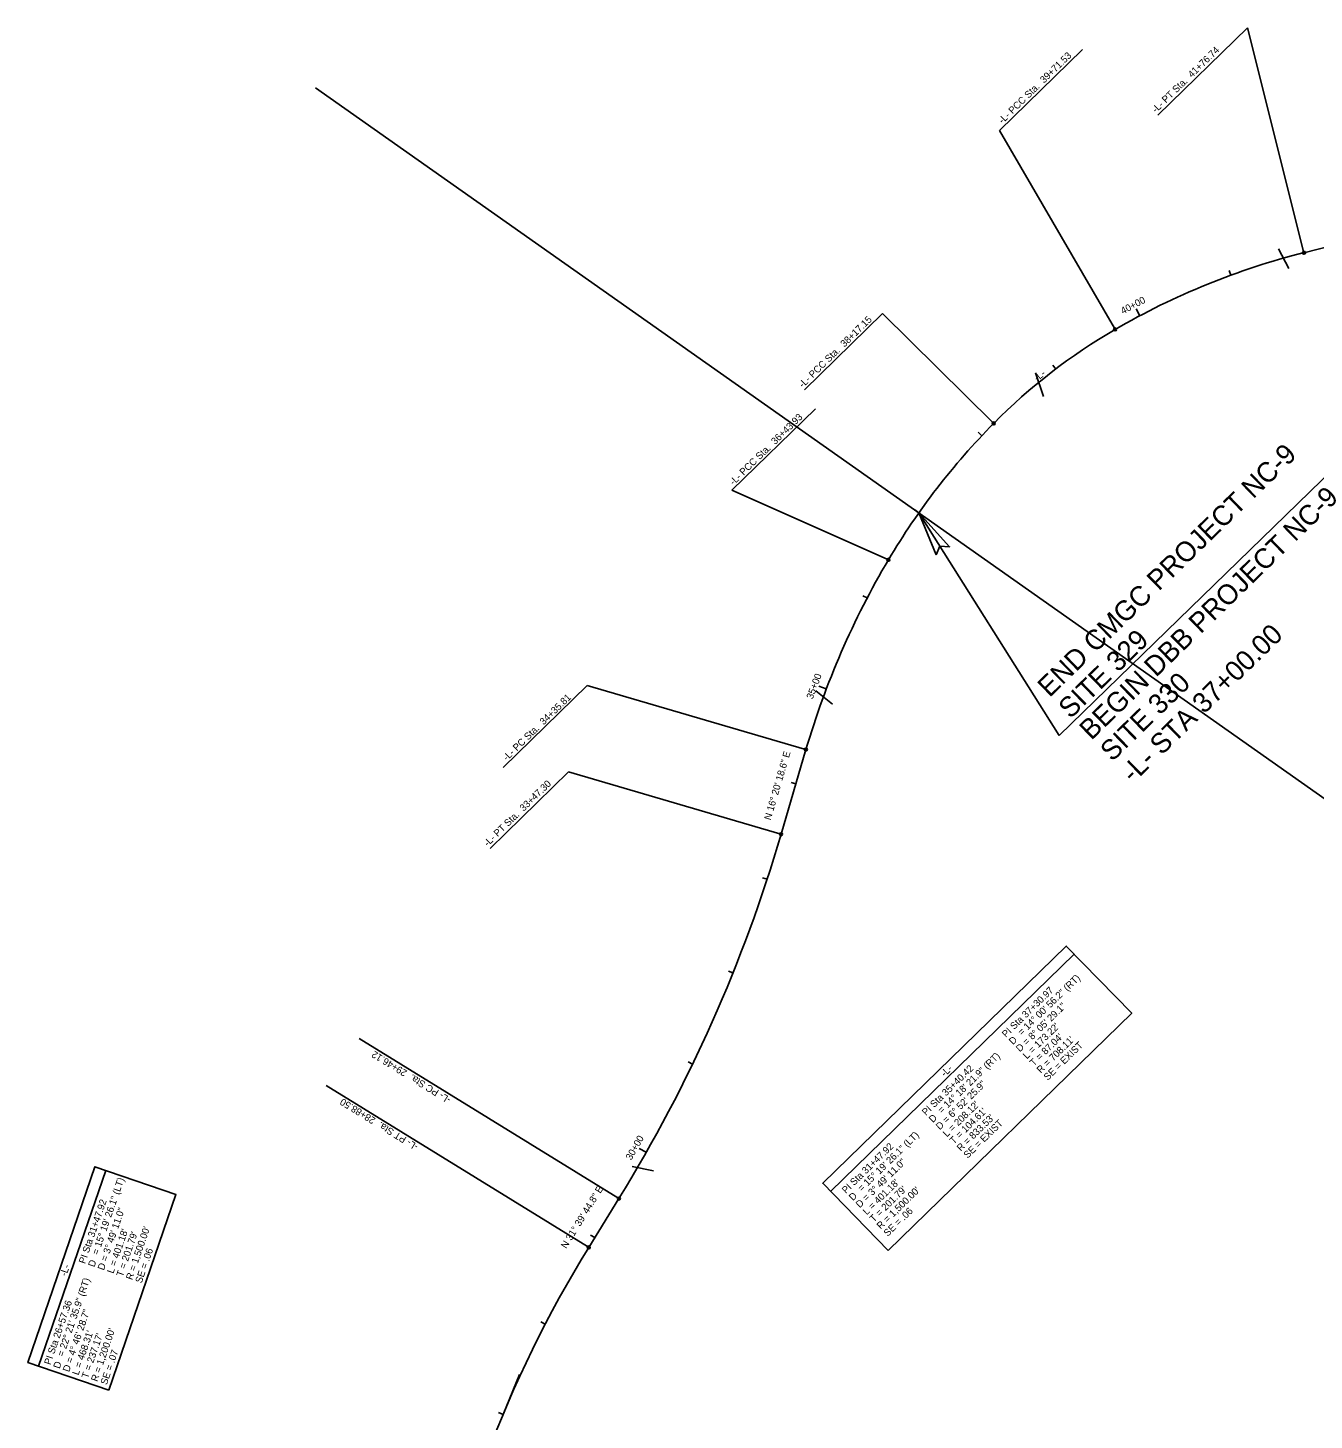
# Model space of a CAD drawing. Extents: x 1019959 to 1023888, y 635993 to 644996.
# Drawn here: x 1020284 to 1021574, y 637770 to 639166 of the extents above; entities that cross this region are included whole.
import ezdxf

# ---------------------------------------------------------------- set-up
doc = ezdxf.new("R2010")
doc.units = 0
for name, color, linetype in [('Cogo Default Point CELL', 7, 'Continuous'), ('COGO Default Point Elevation', 7, 'Continuous'), ('COGO Default Point Number', 7, 'Continuous'), ('Exist Other Culture Well CELL', 7, 'Continuous'), ('Exist Roads EOT', 7, 'Continuous'), ('Exist Structure Minor Pipes CMP 18 Inch Cogo Comment', 7, 'Continuous'), ('Exist Structure Minor Pipes CMP 18 Inch Cogo Number', 7, 'Continuous'), ('Exist Structure Minor Pipes CMP 24 Inch Cogo Number', 7, 'Continuous'), ('Exist Structure Minor Pipes CMP 24 Inch Cogo Point CELL', 7, 'Continuous'), ('Exist Utilities Power Pole CELL', 7, 'Continuous'), ('Exist Utilities Power Pole Cogo Elevation', 7, 'Continuous'), ('Exist Utilities Power Pole Cogo Number', 7, 'Continuous')]:
    doc.layers.add(name, color=color, linetype=linetype)

msp = doc.modelspace()

# ---------------------------------------------------------------- linework, layer by layer
at = {"layer": 'COGO Default Point Elevation'}
for p, q in [((1021490.3, 638918.1), (1021488.6, 638922.8)), ((1021314.7, 638824), (1021311.6, 638828)), ((1021240.5, 638757.1), (1021236.9, 638760.5)), ((1021177.3, 638679.7), (1021173.3, 638682.6)), ((1021125.5, 638594.3), (1021121.1, 638596.6)), ((1021054.1, 638407.9), (1021049.3, 638409.3)), ((1021025.2, 638312.2), (1021020.5, 638313.7)), ((1020990.9, 638218.2), (1020986.3, 638220.1)), ((1020950.5, 638126.8), (1020946, 638129)), ((1020852.3, 637952.7), (1020848.1, 637955.3)), ((1020802.7, 637865.9), (1020798.2, 637868.2)), ((1020760.3, 637775.3), (1020755.7, 637777.3))]:
    msp.add_line(p, q, dxfattribs=at)
at = {"layer": 'COGO Default Point Number'}
for p, q in [((1021399.1, 638877.5), (1021395.3, 638884.5)), ((1021084.5, 638503.1), (1021077.1, 638505.9)), ((1020904, 638038.3), (1020897, 638042.2))]:
    msp.add_line(p, q, dxfattribs=at)
at = {"layer": 'Exist Other Culture Well CELL'}
for p, q in [((1021318.2, 638456.2), (1021612.5, 638742.9)), ((1021177.3, 638679.7), (1021318.2, 638456.2))]:
    msp.add_line(p, q, dxfattribs=at)
at = {"layer": 'Exist Roads EOT'}
for p, q in [((1021506.8, 639166.2), (1021416.9, 639078.6)), ((1021506.8, 639166.2), (1021563.6, 638940.7)), ((1021341.6, 639144.4), (1021258.3, 639063.2)), ((1021373.4, 638865), (1021258.3, 639063.2)), ((1021141, 638879.6), (1021062.6, 638803.2)), ((1021251.4, 638770.5), (1021141, 638879.6)), ((1021073.7, 638784.1), (1020989.9, 638702.4)), ((1021145.6, 638633.4), (1020989.9, 638702.4)), ((1020844.8, 638506.6), (1020760.4, 638424.3)), ((1021062.7, 638442.7), (1020844.8, 638506.6)), ((1020826.1, 638419.8), (1020747.3, 638343.1)), ((1021037.8, 638357.7), (1020826.1, 638419.8)), ((1020875.3, 637992.7), (1020616.2, 638152.5)), ((1020845, 637943.7), (1020582.8, 638105.4))]:
    msp.add_line(p, q, dxfattribs=at)
for centre in [(1021563.6, 638940.7), (1021374.2, 638863.7), (1021252.4, 638769.4), (1021146.9, 638632.6), (1021064.1, 638442.3), (1021039.2, 638357.3), (1020876.5, 637991.9), (1020846.3, 637942.9)]:
    msp.add_circle(centre, 1.5, dxfattribs=at)
at = {"layer": 'Exist Structure Minor Pipes CMP 18 Inch Cogo Comment'}
msp.add_lwpolyline([(1021194.8, 638637.5), (1021177.3, 638679.7), (1021208.2, 638645.7), (1021198.4, 638646.3)], close=True, dxfattribs=at)
at = {"layer": 'Exist Structure Minor Pipes CMP 18 Inch Cogo Number'}
msp.add_line((1021563.6, 638940.7), (1021760.5, 638990.3), dxfattribs=at)
for centre, radius, start, end in [((1021743.1, 638228.3), 734.7, 104.136, 120.1389), ((1021666.3, 638360.4), 581.9, 120.1389, 135.3398), ((1021756.1, 638271.7), 708.1, 135.3398, 149.3554), ((1021864, 638207.8), 833.5, 149.3554, 163.6615)]:
    msp.add_arc(centre, radius, start, end, dxfattribs=at)
at = {"layer": 'Exist Structure Minor Pipes CMP 24 Inch Cogo Number'}
for p, q in [((1020572.4, 639106.2), (1022106.2, 638024.9)), ((1021548.3, 638924.7), (1021538.1, 638944.5)), ((1021302.3, 638796.4), (1021294.2, 638820)), ((1021090.9, 638487.8), (1021074.1, 638501.1)), ((1020911.2, 638019.8), (1020889.8, 638023.9)), ((1020777, 637815.4), (1020760.3, 637775.3))]:
    msp.add_line(p, q, dxfattribs=at)
at = {"layer": 'Exist Structure Minor Pipes CMP 24 Inch Cogo Point CELL'}
for p, q in [((1021039.2, 638357.3), (1021064.1, 638442.3)), ((1020846.3, 637942.9), (1020876.5, 637991.9))]:
    msp.add_line(p, q, dxfattribs=at)
for centre, radius, start, end in [((1019599.8, 638779.3), 1500, 328.3376, 343.6615), ((1021867.7, 637313), 1200, 148.3376, 170.6975)]:
    msp.add_arc(centre, radius, start, end, dxfattribs=at)
at = {"layer": 'Exist Utilities Power Pole CELL'}
for p, q in [((1021563.6, 638940.7), (1021760.5, 638990.3)), ((1021039.2, 638357.3), (1021064.1, 638442.3)), ((1020846.3, 637942.9), (1020876.5, 637991.9))]:
    msp.add_line(p, q, dxfattribs=at)
for centre, radius, start, end in [((1021743.1, 638228.3), 734.7, 104.136, 120.1389), ((1021666.3, 638360.4), 581.9, 120.1389, 135.3398), ((1021756.1, 638271.7), 708.1, 135.3398, 149.3554), ((1021864, 638207.8), 833.5, 149.3554, 163.6615), ((1019599.8, 638779.3), 1500, 328.3376, 343.6615), ((1021867.7, 637313), 1200, 148.3376, 170.6975)]:
    msp.add_arc(centre, radius, start, end, dxfattribs=at)
at = {"layer": 'Exist Utilities Power Pole Cogo Elevation'}
for p, q in [((1021088.9, 637999.1), (1021333.1, 638237)), ((1020294.5, 637823.7), (1020361.8, 638020.1))]:
    msp.add_line(p, q, dxfattribs=at)
for points in [[(1021146.7, 637939.8), (1021390.9, 638177.7), (1021325.1, 638245.2), (1021081, 638007.2)], [(1020365, 637799.6), (1020432.3, 637996), (1020351, 638023.8), (1020283.8, 637827.4)]]:
    msp.add_lwpolyline(points, close=True, dxfattribs=at)

# ---------------------------------------------------------------- texts
at = {"layer": 'Cogo Default Point CELL'}
for s, rotation, p in [('40+00', 27.9189, (1021382.1, 638878.7)), ('35+00', 69.2491, (1021070.8, 638492.3)), ('30+00', 60.3955, (1020888.9, 638029.8))]:
    msp.add_text(s, height=7, rotation=rotation, dxfattribs=at).set_placement(p)
at = {"layer": 'Exist Other Culture Well CELL'}
for s, p in [('END CMGC PROJECT NC-9 ', (1021308.4, 638493.9)), ('BEGIN DBB PROJECT NC-9', (1021350.3, 638450.9)), ('SITE 329', (1021329.3, 638472.4)), ('-L- STA 37+00.00', (1021392.1, 638407.9)), ('SITE 330', (1021371.2, 638429.4))]:
    msp.add_text(s, height=20, rotation=44.2601, dxfattribs=at).set_placement(p)
at = {"layer": 'Exist Roads EOT'}
for s, rotation, p in [('-L- PCC Sta.  39+71.53', 44.2601, (1021261.2, 639069.6)), ('-L- PT Sta.  41+76.74', 44.2601, (1021415.1, 639080.5)), ('-L- PCC Sta.  38+17.15', 44.2601, (1021061, 638804.8)), ('-L- PCC Sta.  36+43.93', 44.2601, (1020991.5, 638707)), ('-L- PC Sta.  34+35.81', 44.2601, (1020764.2, 638430.5)), ('-L- PT Sta.  33+47.30', 44.2601, (1020744.9, 638344.6)), ('-L- PC Sta.  29+46.12', 148.3376, (1020708.6, 638092.7)), ('-L- PT Sta.  28+88.50', 148.3376, (1020676, 638045.6))]:
    msp.add_text(s, height=7, rotation=rotation, dxfattribs=at).set_placement(p)
at = {"layer": 'Exist Utilities Power Pole Cogo Elevation'}
for s, rotation, p in [('= 14%%d 00\' 56.2" (RT)', 44.2601, (1021280.7, 638154.9)), ('PI Sta 37+30.97', 44.2601, (1021264.7, 638152.9)), ('D = 8%%d 05\' 29.1"', 44.2601, (1021278.7, 638138.5)), ("L = 173.22'", 44.2601, (1021285.7, 638131.4)), ('D', 44.2601, (1021271.7, 638145.7)), ("T = 87.04'", 44.2601, (1021292.7, 638124.2)), ("R = 708.11'", 44.2601, (1021299.6, 638117.1)), ('SE = EXIST', 44.2601, (1021306.6, 638109.9)), ('= 14%%d 18\' 21.9" (RT)', 44.2601, (1021200.4, 638076.6)), ('PI Sta 35+40.42', 44.2601, (1021184.5, 638074.6)), ('-L-', 44.2601, (1021203.3, 638113.6)), ('D = 6%%d 52\' 25.9"', 44.2601, (1021198.4, 638060.3)), ("L = 208.12'", 44.2601, (1021205.4, 638053.1)), ("T = 104.61'", 44.2601, (1021212.4, 638046)), ('D', 44.2601, (1021191.4, 638067.5)), ("R = 833.53'", 44.2601, (1021219.4, 638038.8)), ('SE = EXIST', 44.2601, (1021226.3, 638031.7)), ('= 15%%d 19\' 26.1" (LT)', 44.2601, (1021120.2, 637998.4)), ('PI Sta 31+47.92', 44.2601, (1021104.2, 637996.4)), ('D = 3%%d 49\' 11.0"', 44.2601, (1021118.1, 637982.1)), ('= 15%%d 19\' 26.1" (LT)', 71.0872, (1020354.4, 637934.9)), ("L = 401.18'", 44.2601, (1021125.1, 637974.9)), ('D', 44.2601, (1021111.2, 637989.2)), ("T = 201.79'", 44.2601, (1021132.1, 637967.7)), ("R = 1,500.00'", 44.2601, (1021139.1, 637960.6)), ('PI Sta 31+47.92', 71.0872, (1020341.1, 637925.9)), ('D = 3%%d 49\' 11.0"', 71.0872, (1020360, 637919.4)), ('SE = .06', 44.2601, (1021146.1, 637953.4)), ("L = 401.18'", 71.0872, (1020369.5, 637916.2)), ("T = 201.79'", 71.0872, (1020378.9, 637912.9)), ("R = 1,500.00'", 71.0872, (1020388.4, 637909.7)), ('SE = .06', 71.0872, (1020397.8, 637906.4)), ('D', 71.0872, (1020350.5, 637922.6)), ('-L-', 71.0872, (1020322.3, 637913.5)), ('= 22%%d 21\' 35.9" (RT)', 71.0872, (1020319.5, 637832.9)), ('PI Sta 26+57.36', 71.0872, (1020306.4, 637824.5)), ('D = 4%%d 46\' 28.7"', 71.0872, (1020325.1, 637817.4)), ("L = 468.31'", 71.0872, (1020334.5, 637814.2)), ("T = 237.17'", 71.0872, (1020344, 637810.9)), ("R = 1,200.00'", 71.0872, (1020353.4, 637807.7)), ('D', 71.0872, (1020315.6, 637820.7)), ('SE = .07', 71.0872, (1020362.9, 637804.5))]:
    msp.add_text(s, height=7, rotation=rotation, dxfattribs=at).set_placement(p)
at = {"layer": 'Exist Utilities Power Pole Cogo Number'}
for s, rotation, p in [('-L-', 37.7394, (1021295.9, 638811.4)), ('N 16%%d 20\' 18.6" E', 73.6615, (1021028.7, 638371)), ('N 31%%d 39\' 44.8" E', 58.3376, (1020823.8, 637941.1))]:
    msp.add_text(s, height=7, rotation=rotation, dxfattribs=at).set_placement(p)

doc.saveas('drawing.dxf')
